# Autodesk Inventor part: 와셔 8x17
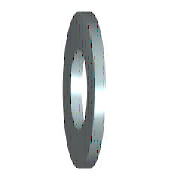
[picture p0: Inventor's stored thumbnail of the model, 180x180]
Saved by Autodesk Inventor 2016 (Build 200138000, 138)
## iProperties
IsCustomPart: 1
Created: 2012-02
Part Number: 와셔 8x17
Material: 강철, 연강
Description: 평면 와셔
Document SubType Name: Modeling
Standard: KS B 1326
Designer: mduedu
Standards Organization: KS
Language: ko-KR
Size Designation: 8x17
Categories: <MemberInstance><Categories><Category DisplayName="조임쇠" InternalName="e4da775c-781d-43d5-af7c-5136215cf5a6" Mnemonic="FSTN"><Category DisplayName="와셔" InternalN
Density: 1 g/cm^3
Appearance: 노란색
Author: mduedu
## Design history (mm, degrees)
sketch "스케치"
  geometry: C1 r 8.5 at (0, 0); C2 r 4.2 at (0, 0); 1 further point
  constraints: 2 centre point, 2 coincident
  dimensions: "d0" = 8.4 diameter of C2 (= SD1); "d1" = 17 diameter of C1 (= SD2)
extrude "본체" new body sketch "스케치" distance "d2" = 1.6 (= SD); taper "d3" = 0 deg
workaxis "Work Axis1"
workplane "Work Plane1"
body "Solid1"
other parameters: "SD1" = 8.4 [user parameter; used in 1 equation term], "SD2" = 17 [user parameter; used in 1 equation term], "SD" = 1.6 [user parameter; used in 1 equation term], "d4" = 0, "d5" = 0, "d6" = 0, "d7" = 0, "NND" = 8 [user parameter]
